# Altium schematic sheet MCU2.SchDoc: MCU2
size A3; DocumentNumber: MB1144; Revision: C-02; SheetNumber: 4; SheetTotal: 25; PageSetup: Record=PageOptions|CenterHorizontal=True|CenterVertical=True|PrintScale=1.04|XCorrection=1.00|YCorrection=1.00|PrintKind=1|BorderSize=5000000|LeftOffset=0|BottomOffset=0|Orientation=2|PaperLength=1000|PaperWidth=1000|Scale=100|PaperSource=7|PrintQuality=600|MediaType=1|DitherType=10|PaperKind=A3|PrintScaleMode=1; Project: STM32L476G-EVAL
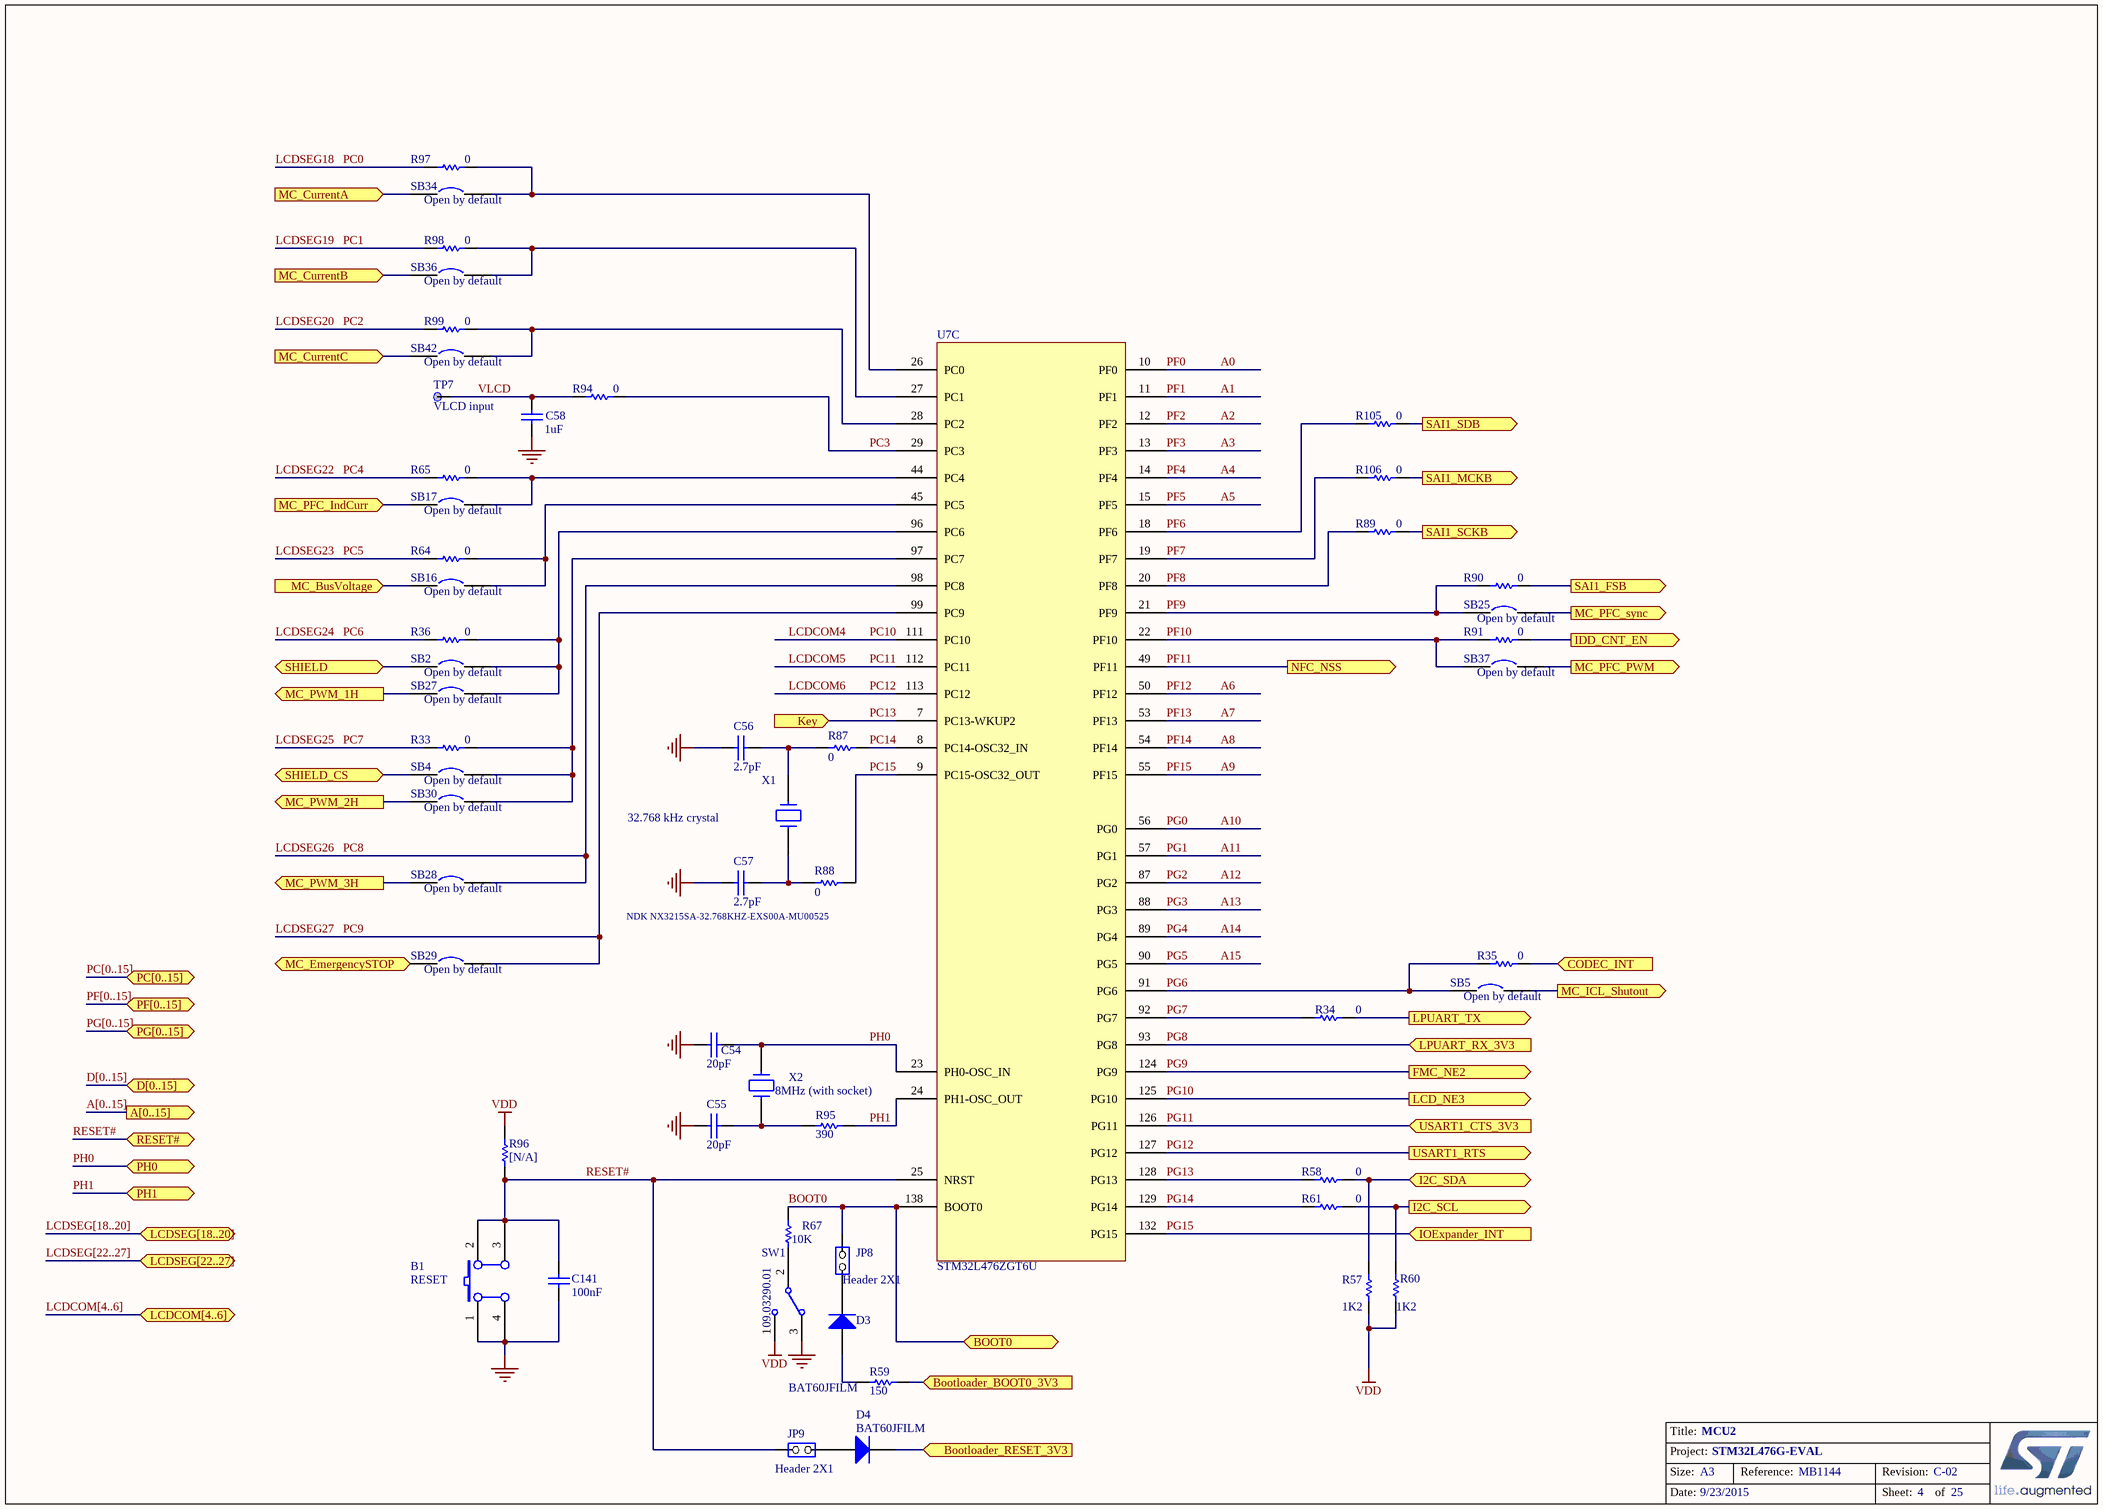
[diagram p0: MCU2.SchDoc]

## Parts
B1  RESET  [PB10]
C54  20pF  [0402R]
C55  20pF  [0402R]
C56  2.7pF  [0603C]
C57  2.7pF  [0603C]
C58  1uF  [0603C]
C141  100nF  [0402C]
D3  BAT60JFILM  [SOD-323]
D4  BAT60JFILM  [SOD-323]
JP8  Header 2X1  [SIP2]
JP9  Header 2X1  [SIP2]
R33  0  [SB_0603]
R34  0  [0603R]
R35  0  [SB_0603]
R36  0  [SB_0603]
R57  1K2  [0402R]
R58  0  [0603R]
R59  150  [0402R]
R60  1K2  [0402R]
R61  0  [0603R]
R64  0  [SB_0603]
R65  0  [SB_0603]
R67  10K  [0402R]
R87  0  [0603R]
R88  0  [0603R]
R89  0  [0603R]
R90  0  [SB_0603]
R91  0  [SB_0603]
R94  0  [0603R]
R95  390  [0603R]
R96  [N/A]  [0603R]
R97  0  [SB_0603]
R98  0  [SB_0603]
R99  0  [SB_0603]
R105  0  [0603R]
R106  0  [0603R]
SB2  Open by default  [SB_0603]
SB4  Open by default  [SB_0603]
SB5  Open by default  [SB_0603]
SB16  Open by default  [SB_0603]
SB17  Open by default  [SB_0603]
SB25  Open by default  [SB_0603]
SB27  Open by default  [SB_0603]
SB28  Open by default  [SB_0603]
SB29  Open by default  [SB_0603]
SB30  Open by default  [SB_0603]
SB34  Open by default  [SB_0603]
SB36  Open by default  [SB_0603]
SB37  Open by default  [SB_0603]
SB42  Open by default  [SB_0603]
SW1  09.03290.01  [SW1_3TH_2R54_10X2R5]
TP7  TP Name: VLCD input  [TP]  (hidden comment: [N/A])
U7  STM32L476ZGT6U  [TQFP144_0R5_22X22_SOCKET]  (part C of 3)
X1  NDK NX3215SA-32.768KHZ-EXS00A-MU00525  [XTAL_2SM_3R2X1R5]
X2  8MHz (with socket)  [XTAL_SOCKET]

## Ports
A[0..15] (out), BOOT0, Bootloader_BOOT0_3V3 (in), Bootloader_RESET_3V3 (in), CODEC_INT (in), D[0..15] (bidir), FMC_NE2 (out), I2C_SCL (out), I2C_SDA (bidir), IDD_CNT_EN (out), IOExpander_INT (in), Key (in), LCD_NE3 (out), LCDCOM[4..6] (bidir), LCDSEG[18..20] (bidir), LCDSEG[22..27] (bidir), LPUART_RX_3V3 (in), LPUART_TX (out), MC_BusVoltage (in), MC_CurrentA (in), MC_CurrentB (in), MC_CurrentC (in), MC_EmergencySTOP (in), MC_ICL_Shutout (out), MC_PFC_IndCurr (in), MC_PFC_PWM (out), MC_PFC_sync (out), MC_PWM_1H (out), MC_PWM_2H (out), MC_PWM_3H (out), NFC_NSS (out), PC[0..15] (bidir), PF[0..15] (bidir), PG[0..15] (bidir), PH0, PH1, RESET# (bidir), SAI1_FSB (out), SAI1_MCKB (out), SAI1_SCKB (out), SAI1_SDB (out), SHIELD, SHIELD_CS, USART1_CTS_3V3 (in), USART1_RTS (out)

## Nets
GND: B1.1(A0) B1.4(A1) C54.2 C55.2 C56.2 C57.2 C58.1 C141.1 SW1.3
VDD: R57.2 R60.2 R96.2 SW1.1
A0: U7.10(PF0)  [also labelled PF0]
A1: U7.11(PF1)  [also labelled PF1]
A2: U7.12(PF2)  [also labelled PF2]
A3: U7.13(PF3)  [also labelled PF3]
A4: U7.14(PF4)  [also labelled PF4]
A5: U7.15(PF5)  [also labelled PF5]
A6: U7.50(PF12)  [also labelled PF12]
A7: U7.53(PF13)  [also labelled PF13]
A8: U7.54(PF14)  [also labelled PF14]
A9: U7.55(PF15)  [also labelled PF15]
A10: U7.56(PG0)  [also labelled PG0]
A11: U7.57(PG1)  [also labelled PG1]
A12: U7.87(PG2)  [also labelled PG2]
A13: U7.88(PG3)  [also labelled PG3]
A14: U7.89(PG4)  [also labelled PG4]
A15: U7.90(PG5)  [also labelled PG5]
BOOT0: JP8.1(COMMON) R67.1 U7.138(BOOT0) ; port BOOT0
Bootloader_BOOT0_3V3: R59.2 ; port Bootloader_BOOT0_3V3
Bootloader_RESET_3V3: D4.2(K) ; port Bootloader_RESET_3V3
CODEC_INT: R35.1 ; port CODEC_INT
I2C_SCL: R60.1 R61.1 ; port I2C_SCL
I2C_SDA: R57.1 R58.1 ; port I2C_SDA
IDD_CNT_EN: R91.1 ; port IDD_CNT_EN
LCDCOM4: U7.111(PC10)  [also labelled PC10]
LCDCOM5: U7.112(PC11)  [also labelled PC11]
LCDCOM6: U7.113(PC12)  [also labelled PC12]
LCDSEG18: R97.1  [also labelled PC0]
LCDSEG19: R98.1  [also labelled PC1]
LCDSEG20: R99.1  [also labelled PC2]
LCDSEG22: R65.1  [also labelled PC4]
LCDSEG23: R64.1  [also labelled PC5]
LCDSEG24: R36.1  [also labelled PC6]
LCDSEG25: R33.1  [also labelled PC7]
LCDSEG26: SB28.2 U7.98(PC8)  [also labelled PC8]
LCDSEG27: SB29.2 U7.99(PC9)  [also labelled PC9]
LPUART_TX: R34.1 ; port LPUART_TX
MC_BusVoltage: SB16.1 ; port MC_BusVoltage
MC_CurrentA: SB34.1 ; port MC_CurrentA
MC_CurrentB: SB36.1 ; port MC_CurrentB
MC_CurrentC: SB42.1 ; port MC_CurrentC
MC_EmergencySTOP: SB29.1 ; port MC_EmergencySTOP
MC_ICL_Shutout: SB5.2 ; port MC_ICL_Shutout
MC_PFC_IndCurr: SB17.1 ; port MC_PFC_IndCurr
MC_PFC_PWM: SB37.2 ; port MC_PFC_PWM
MC_PFC_sync: SB25.2 ; port MC_PFC_sync
MC_PWM_1H: SB27.1 ; port MC_PWM_1H
MC_PWM_2H: SB30.1 ; port MC_PWM_2H
MC_PWM_3H: SB28.1 ; port MC_PWM_3H
PC3: R94.1 U7.29(PC3)
PC13: U7.7(PC13-WKUP2) ; port Key
PC14: R87.2 U7.8(PC14-OSC32_IN)
PC15: R88.2 U7.9(PC15-OSC32_OUT)
PF6: R105.2 U7.18(PF6)
PF7: R106.2 U7.19(PF7)
PF8: R89.2 U7.20(PF8)
PF9: R90.2 SB25.1 U7.21(PF9)
PF10: R91.2 SB37.1 U7.22(PF10)
PF11: U7.49(PF11) ; port NFC_NSS
PG6: R35.2 SB5.1 U7.91(PG6)
PG7: R34.2 U7.92(PG7)
PG8: U7.93(PG8) ; port LPUART_RX_3V3
PG9: U7.124(PG9) ; port FMC_NE2
PG10: U7.125(PG10) ; port LCD_NE3
PG11: U7.126(PG11) ; port USART1_CTS_3V3
PG12: U7.127(PG12) ; port USART1_RTS
PG13: R58.2 U7.128(PG13)
PG14: R61.2 U7.129(PG14)
PG15: U7.132(PG15) ; port IOExpander_INT
PH0: C54.1 U7.23(PH0-OSC_IN) X2.2 ; port PH0
PH1: R95.1 U7.24(PH1-OSC_OUT) ; port PH1
RESET#: B1.2(B0) B1.3(B1) C141.2 JP9.1(COMMON) R96.1 U7.25(NRST) ; port RESET#
SAI1_FSB: R90.1 ; port SAI1_FSB
SAI1_MCKB: R106.1 ; port SAI1_MCKB
SAI1_SCKB: R89.1 ; port SAI1_SCKB
SAI1_SDB: R105.1 ; port SAI1_SDB
SHIELD: SB2.1 ; port SHIELD
SHIELD_CS: SB4.1 ; port SHIELD_CS
VLCD: C58.2 R94.2 TP7.1
NetC55_1: C55.1 R95.2 X2.1
NetC56_1: C56.1 R87.1 X1.2
NetC57_1: C57.1 R88.1 X1.1
NetD3_1: D3.1(A) R59.1
NetD3_2: D3.2(K) JP8.2(NO)
NetD4_1: D4.1(A) JP9.2(NO)
NetR33_2: R33.2 SB4.2 SB30.2 U7.97(PC7)
NetR36_2: R36.2 SB2.2 SB27.2 U7.96(PC6)
NetR64_2: R64.2 SB16.2 U7.45(PC5)
NetR65_2: R65.2 SB17.2 U7.44(PC4)
NetR67_2: R67.2 SW1.2
NetR97_2: R97.2 SB34.2 U7.26(PC0)
NetR98_2: R98.2 SB36.2 U7.27(PC1)
NetR99_2: R99.2 SB42.2 U7.28(PC2)

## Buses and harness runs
bus A[0..15] = port A[0..15]
bus D[0..15] = port D[0..15]
bus LCDCOM[4..6] = port LCDCOM[4..6]
bus LCDSEG[18..20] = port LCDSEG[18..20]
bus LCDSEG[22..27] = port LCDSEG[22..27]
bus PC[0..15] = port PC[0..15]
bus PF[0..15] = port PF[0..15]
bus PG[0..15] = port PG[0..15]

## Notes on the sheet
- 32.768 kHz crystal

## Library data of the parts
B1 = SW PUSHBUTTON: SE PUSHBUTTON; Ordered by: Subcon; Comments: no comment; Assembly: Black; ECCN_US/EU: NA
C54-C57 = CAP: Capacitor; Ordered by: Subcon; ECCN_US/EU: NA
C58 = CAP: Capacitor; Value: 100nF; Ordered by: Subcon; ECCN_US/EU: NA
C141 = CAP: Capacitor; Value: 100pF; Ordered by: Subcon; ECCN_US/EU: NA
D3 D4 = Diode: Default Diode; Code - JEDEC: DO-214-AB; Ordered by: ST; ECCN_US/EU: EAR99/NEC; Ref St: 9151097
JP8 JP9 = JP2: Ordered by: Subcon; ECCN_US/EU: NA
R33 R34 R36 R57 R58 R60 R61 R64 R65 R87 R88 R95 R97-R99 = Res1: Resistor; Value: 1K; Ordered by: Subcon; ECCN_US/EU: NA
R35 R59 R67 R89-R91 R94 R105 R106 = res1: Resistor; Value: 1K; Ordered by: Subcon; ECCN_US/EU: NA
R96 = res1: Resistor; Value: 1K; Ordered by: Subcon; ECCN_US/EU: NA; Fitted: NO
SB2 SB4 SB5 SB16 SB17 SB25 SB27-SB30 SB34 SB36 SB37 SB42 = Circuit Breaker: Ordered by: Subcon; Comments: Solder bridge; Fitted: NO; ECCN_US/EU: NA
SW1 = SW-SPDT: SPDT Subminiature Toggle Switch, Right Angle Mounting, Vertical Actuation; Revision 1: Jul-2002: Re-released for DXP Platform.; Revision 2: 17-Dec-2003: Schematic revised, PCB Footprint replaced.; Ordered by: Subcon; ECCN_US/EU: NA
TP7 = TP: Ordered by: Subcon; Fitted or not fitted: NO; ECCN_US/EU: NA; Fitted: NO
U7 = STM32L476_TQFP144: Manuf_Part_1: STM32L476ZGT6U cut1.3; Ordered by: ST; ECCN_US/EU: 3A991A2/NEC; Assembly: MCU; Ref St: 9175195
X1 = CRYSTAL_32K: Crystal; Ordered by: ST; ECCN_US/EU: NA
X2 = CRYSTAL: Manuf_1: jfvny; Manuf_Part_1: HC-49S-C16QSA-8M; Ordered by: Subcon; ECCN_US/EU: NA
